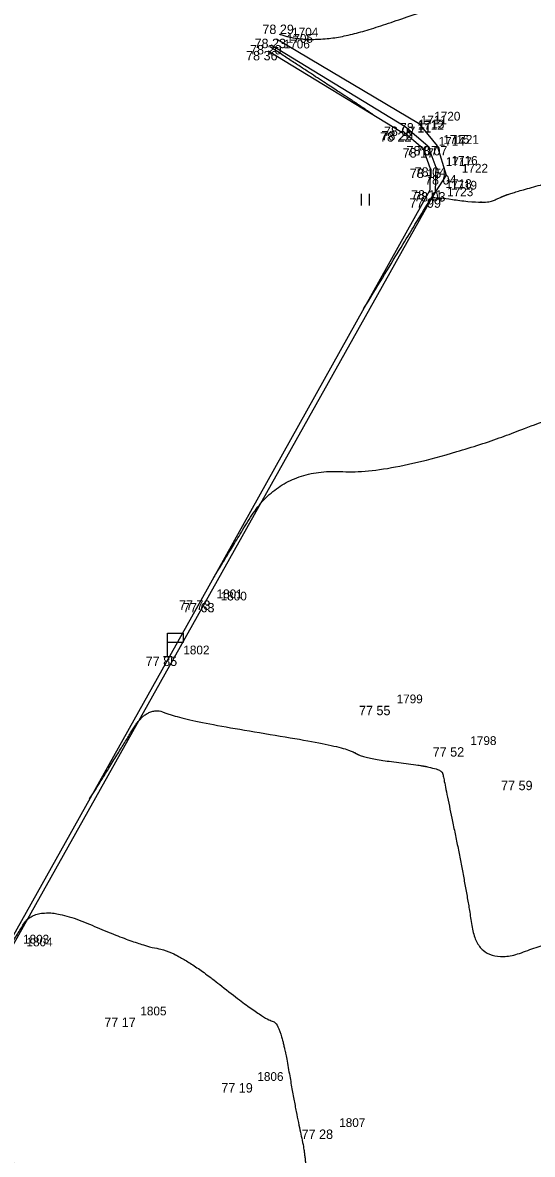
# Model space of a CAD drawing. Extents: x -704017 to -701500, y -1008977 to -1008450.
# Drawn here: x -701574.39 to -701558.14, y -1008519.37 to -1008483.29 of the extents above; entities that cross this region are included whole.
import ezdxf

# ---------------------------------------------------------------- set-up
doc = ezdxf.new("R2010")
doc.units = 0
for name, color, linetype in [('Z_body', 7, 'Continuous'), ('Z_body_cisla', 7, 'Continuous'), ('Z_body_vysky', 7, 'Continuous'), ('Z_dopravni_znaceni', 7, 'Continuous'), ('Z_komunikace', 7, 'Continuous'), ('Z_obruby', 7, 'Continuous'), ('Z_popis', 7, 'Continuous'), ('Z_rozhrani_ploch', 7, 'Continuous'), ('Z_vrstevnice_hlavni', 7, 'Continuous'), ('Z_vrstevnice_vedlejsi', 7, 'Continuous')]:
    doc.layers.add(name, color=color, linetype=linetype)

# ---------------------------------------------------------------- blocks, each defined once
blk = doc.blocks.new('POINT_DISPLAY')
blk.add_line((0, 0), (0, 0))
blk = doc.blocks.new('Z306')
for p, q in [((-0.13, 0.17), (-0.13, -0.2)), ((0.13, 0.17), (0.13, -0.2))]:
    blk.add_line(p, q)
blk = doc.blocks.new('Z524')
for p, q in [((0, 0), (0, 0.75)), ((0, 0.75), (0.5, 0.75)), ((0.5, 0.75), (0.5, 0.45)), ((0.5, 0.45), (0, 0.45)), ((-0.13, 0), (0.13, 0))]:
    blk.add_line(p, q)

msp = doc.modelspace()

# ---------------------------------------------------------------- linework, layer by layer
at = {"layer": 'Z_komunikace'}
for p, q in [((-701566.3, -1008483.8), (-701561.77, -1008486.49)), ((-701561.77, -1008486.49), (-701561.18, -1008487.22)), ((-701561.18, -1008487.22), (-701560.89, -1008488.15)), ((-701560.89, -1008488.15), (-701561.24, -1008488.69)), ((-701561.36, -1008488.89), (-701568.58, -1008501.79)), ((-701561.24, -1008488.69), (-701561.36, -1008488.89)), ((-701568.58, -1008501.79), (-701574.77, -1008512.82))]:
    msp.add_line(p, q, dxfattribs=at)
at = {"layer": 'Z_obruby'}
for p, q in [((-701566.57, -1008484.19), (-701562.3, -1008486.78)), ((-701562.3, -1008486.78), (-701562.28, -1008486.74)), ((-701562.28, -1008486.74), (-701561.63, -1008487.29)), ((-701561.63, -1008487.29), (-701561.4, -1008487.94)), ((-701561.4, -1008487.94), (-701561.41, -1008488.63)), ((-701561.41, -1008488.63), (-701568.71, -1008501.71)), ((-701568.71, -1008501.71), (-701574.88, -1008512.72))]:
    msp.add_line(p, q, dxfattribs=at)
at = {"layer": 'Z_rozhrani_ploch'}
for p, q in [((-701566.47, -1008484), (-701562.2, -1008486.6)), ((-701562.2, -1008486.6), (-701561.48, -1008487.22)), ((-701561.48, -1008487.22), (-701561.22, -1008487.9)), ((-701561.22, -1008487.9), (-701561.24, -1008488.69))]:
    msp.add_line(p, q, dxfattribs=at)
at = {"layer": 'Z_vrstevnice_hlavni'}
for points in [[(-701563.523, -1008492.416), (-701561.364, -1008488.868), (-701561.33, -1008488.84), (-701559.616, -1008489.067), (-701559.17, -1008488.86), (-701558.806, -1008488.715), (-701556.747, -1008488.152), (-701551.424, -1008485.828), (-701548.541, -1008484.93), (-701547.793, -1008487.034), (-701547.345, -1008487.785), (-701546.655, -1008490.435), (-701546.195, -1008493.568), (-701544.695, -1008493.396), (-701542.113, -1008492.839), (-701540.403, -1008492.427), (-701540.947, -1008493.438), (-701543.588, -1008498.329), (-701542.275, -1008496.175), (-701541.076, -1008494.261), (-701540.681, -1008493.598), (-701539.195, -1008491.491), (-701538.905, -1008491.085), (-701538.579, -1008490.44), (-701538.385, -1008490.335), (-701537.853, -1008490.073), (-701537.758, -1008490.007), (-701537.56, -1008489.947), (-701536.63, -1008490.24), (-701537.148, -1008490.575), (-701536.966, -1008490.753), (-701536.934, -1008490.836), (-701536.925, -1008490.831)], [(-701579.898, -1008517.403), (-701579.435, -1008517.461), (-701579.227, -1008517.484), (-701578.62, -1008517.429), (-701578.136, -1008517.429), (-701578.069, -1008517.412), (-701577.945, -1008517.378), (-701577.257, -1008518.262), (-701570.798, -1008521.775), (-701570.216, -1008525.84), (-701569.854, -1008527.425), (-701569.965, -1008531.811), (-701569.749, -1008533.131), (-701567.868, -1008535.228), (-701564.47, -1008534.54), (-701566.364, -1008538.155), (-701564.827, -1008536.493), (-701563.84, -1008535.42), (-701563.611, -1008535.062), (-701558.382, -1008525.994), (-701558.01, -1008525.615), (-701558.155, -1008525.52), (-701557.85, -1008525.054), (-701557.738, -1008524.883), (-701557.437, -1008525.043), (-701555.858, -1008523.377), (-701555.523, -1008523.061), (-701555.52, -1008523.052), (-701555.478, -1008523.064), (-701555.451, -1008523.038), (-701554.427, -1008521.334), (-701552.912, -1008518.78), (-701552.83, -1008518.643), (-701552.822, -1008518.618), (-701552.869, -1008518.575), (-701552.419, -1008517.944), (-701552.058, -1008517.342), (-701550.92, -1008515.45), (-701550.945, -1008516.008)]]:
    msp.add_open_spline(points, degree=2, dxfattribs=at)
at = {"layer": 'Z_vrstevnice_vedlejsi'}
for points in [[(-701566.217, -1008483.65), (-701565.099, -1008484.048), (-701561.697, -1008482.994), (-701554.574, -1008480.325), (-701552.933, -1008479.738), (-701548.247, -1008478.385), (-701545.471, -1008478.123), (-701544.76, -1008478.78), (-701541.538, -1008477.025), (-701541.151, -1008483.458), (-701540.999, -1008484.017), (-701540.73, -1008483.958), (-701540.707, -1008483.933), (-701540.657, -1008483.957), (-701540.396, -1008483.716), (-701536.443, -1008481.725)], [(-701563.215, -1008486.225), (-701563.621, -1008485.943), (-701564.912, -1008485.104), (-701566.501, -1008484.059)], [(-701568.326, -1008501.022), (-701568.145, -1008500.724), (-701566.173, -1008497.49), (-701562.238, -1008497.715), (-701553.13, -1008494.24), (-701552.816, -1008497.54), (-701552.616, -1008499.377), (-701552.857, -1008504.947), (-701549.646, -1008504.426), (-701547.07, -1008504.107), (-701548.25, -1008506.306), (-701549.43, -1008508.556), (-701548.982, -1008507.944), (-701548.02, -1008506.506), (-701544.933, -1008502.149), (-701543.137, -1008499.337), (-701541.934, -1008497.365), (-701539.958, -1008494.049), (-701539.147, -1008492.9), (-701537.953, -1008491.224), (-701537.813, -1008490.946), (-701537.452, -1008490.751), (-701537.116, -1008491.081), (-701537.102, -1008491.117), (-701537.047, -1008491.085)], [(-701572.258, -1008508.041), (-701571.31, -1008506.526), (-701570.409, -1008505.049), (-701569.303, -1008505.526), (-701564.045, -1008506.378), (-701563.587, -1008506.741), (-701561.032, -1008507.039), (-701560.968, -1008507.406), (-701560.286, -1008510.688), (-701559.852, -1008513.504), (-701556.678, -1008512.221), (-701554.955, -1008514.272), (-701552.862, -1008514.257), (-701553.413, -1008515.331), (-701553.7, -1008516.053), (-701553.645, -1008516.425), (-701553.448, -1008516.116), (-701550.42, -1008511.691), (-701546.729, -1008506.481), (-701542.438, -1008499.763), (-701539.564, -1008495.053), (-701539.235, -1008494.5), (-701539.1, -1008494.308), (-701538.245, -1008493.108), (-701537.193, -1008491.353), (-701537.17, -1008491.34)], [(-701575.752, -1008514.26), (-701574.817, -1008512.777), (-701573.926, -1008511.316), (-701570.695, -1008512.711), (-701569.42, -1008512.917), (-701566.67, -1008515.095), (-701566.175, -1008515.153), (-701565.67, -1008518.087), (-701565.342, -1008519.528), (-701565.377, -1008520.923), (-701564.84, -1008526.43), (-701562.564, -1008525.59), (-701558.639, -1008524.363), (-701560.089, -1008527.07), (-701561.075, -1008528.916), (-701559.86, -1008527.2), (-701558.867, -1008525.971), (-701557.302, -1008523.273), (-701557.219, -1008523.184), (-701556.594, -1008522.597), (-701556.513, -1008522.355), (-701556.357, -1008522.401), (-701554.888, -1008520.254), (-701553.753, -1008518.595), (-701553.721, -1008518.39), (-701553.438, -1008518.164), (-701553.603, -1008518.013), (-701550.512, -1008513.673), (-701549.42, -1008512.077), (-701548.525, -1008510.814), (-701546.565, -1008507.745), (-701545.255, -1008505.496), (-701544.661, -1008504.504)]]:
    msp.add_open_spline(points, degree=2, dxfattribs=at)

# ---------------------------------------------------------------- block references
at = {"layer": 'Z_body'}
for p in [(-701566.05, -1008483.35), (-701566.3, -1008483.8), (-701566.57, -1008484.19), (-701566.47, -1008484), (-701562.3, -1008486.78), (-701562.28, -1008486.74), (-701562.2, -1008486.6), (-701561.77, -1008486.49), (-701561.63, -1008487.29), (-701561.48, -1008487.22), (-701561.18, -1008487.22), (-701561.22, -1008487.9), (-701561.4, -1008487.94), (-701560.89, -1008488.15), (-701561.41, -1008488.63), (-701561.36, -1008488.89), (-701561.24, -1008488.69), (-701568.71, -1008501.71), (-701568.58, -1008501.79), (-701569.77, -1008503.5), (-701562.97, -1008505.07), (-701560.62, -1008506.39), (-701558.44, -1008507.46), (-701571.14, -1008515.01), (-701567.41, -1008517.1), (-701564.8, -1008518.58)]:
    msp.add_blockref('POINT_DISPLAY', p, dxfattribs=at)
at = {"layer": 'Z_dopravni_znaceni'}
msp.add_blockref('Z524', (-701569.77, -1008503.5), dxfattribs=at)
at = {"layer": 'Z_popis'}
msp.add_blockref('Z306', (-701563.47, -1008488.92), dxfattribs=at)

# ---------------------------------------------------------------- texts
at = {"layer": 'Z_body_cisla'}
for s, p in [('1704', (-701565.8, -1008483.73)), ('1706', (-701566.07, -1008484.11)), ('1705', (-701565.97, -1008483.93)), ('1712', (-701561.8, -1008486.7)), ('1713', (-701561.78, -1008486.66)), ('1711', (-701561.7, -1008486.53)), ('1720', (-701561.27, -1008486.41)), ('1714', (-701561.13, -1008487.21)), ('1715', (-701560.98, -1008487.15)), ('1721', (-701560.68, -1008487.15)), ('1716', (-701560.72, -1008487.82)), ('1717', (-701560.9, -1008487.86)), ('1722', (-701560.39, -1008488.07)), ('1718', (-701560.91, -1008488.56)), ('1723', (-701560.86, -1008488.82)), ('1719', (-701560.74, -1008488.61)), ('1801', (-701568.21, -1008501.64)), ('1800', (-701568.08, -1008501.71)), ('1802', (-701569.27, -1008503.43)), ('1799', (-701562.47, -1008504.99)), ('1798', (-701560.12, -1008506.32)), ('1803', (-701574.38, -1008512.65)), ('1804', (-701574.27, -1008512.74)), ('1805', (-701570.64, -1008514.94)), ('1806', (-701566.91, -1008517.03)), ('1807', (-701564.3, -1008518.5))]:
    msp.add_text(s, height=0.28, dxfattribs=at).set_placement(p)
at = {"layer": 'Z_body_vysky'}
for s, p in [('78 29', (-701566.75, -1008483.65)), ('78 23', (-701567, -1008484.1)), ('78 36', (-701567.27, -1008484.49)), ('78 20', (-701567.145, -1008484.3)), ('78 22', (-701563, -1008487.08)), ('78 20', (-701562.955, -1008487.04)), ('78 07', (-701562.875, -1008486.9)), ('78 11', (-701562.37, -1008486.79)), ('78 17', (-701562.28, -1008487.59)), ('78 07', (-701562.155, -1008487.52)), ('78 07', (-701561.855, -1008487.52)), ('78 04', (-701561.895, -1008488.2)), ('78 15', (-701562.05, -1008488.24)), ('78 04', (-701561.565, -1008488.45)), ('78 11', (-701562.01, -1008488.93)), ('77 99', (-701562.06, -1008489.19)), ('78 03', (-701561.915, -1008488.99)), ('77 73', (-701569.41, -1008502.01)), ('77 63', (-701569.28, -1008502.09)), ('77 85', (-701570.47, -1008503.8)), ('77 55', (-701563.67, -1008505.37)), ('77 52', (-701561.32, -1008506.69)), ('77 59', (-701559.14, -1008507.76)), ('77 17', (-701571.79, -1008515.31)), ('77 19', (-701568.06, -1008517.4)), ('77 28', (-701565.5, -1008518.88))]:
    msp.add_text(s, height=0.3, dxfattribs=at).set_placement(p)

doc.saveas('drawing.dxf')
